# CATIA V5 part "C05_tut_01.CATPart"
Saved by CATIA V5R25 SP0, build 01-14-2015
Part number: Part1
Bounding box of the stored display mesh (mm): x -20 to 20, y 0 to 95, z 0 to 40
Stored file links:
  E:\ashutosh\Academics\Catia\CATIA V5-6R2013_partfiles\Tutorials_ver_2\C05_tut_01.CATPart
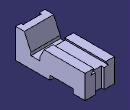
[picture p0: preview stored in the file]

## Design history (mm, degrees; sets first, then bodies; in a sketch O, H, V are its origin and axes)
Body1 (main body)
  Sketch1 on yz-plane, origin (0, 0, 0), H (0, 1, 0), V (0, 0, 1)
    point P1 (0, 0)
    line L1 (0, 0) -> (0, 40)
    line L2 (0, 40) -> (12, 40)
    line L3 (12, 40) -> (21, 20)
    line L4 (21, 20) -> (21, 16)
    line L5 (21, 16) -> (33, 16)
    line L6 (33, 16) -> (33, 20)
    point P7 (33, 20)
    line L7 (33, 20) -> (39, 32)
    point P8 (39, 32)
    line L8 (39, 32) -> (95, 32)
    line L9 (95, 32) -> (95, 0)
    point P10 (95, 0)
    line L10 (95, 0) -> (79, 0)
    line L11 (79, 0) -> (79, 6)
    line L12 (79, 6) -> (47, 6)
    line L13 (47, 6) -> (47, 0)
    point P14 (47, 0)
    line L14 (47, 0) -> (0, 0)
    reference intersected line E1 through (0, 0) direction (0, 1) from zx-plane
    length L1 = 40
    length L2 = 12
    length L8 = 56
    distance P8 P7 V = 12
    distance L1 L9 = 95
    distance P8 P7 H = 6
    length L9 = 32
    length L12 = 32
    length L11 = 6
    length L4 = 4
    distance L5 L14 = 16
    length L5 = 12
    distance L11 L9 = 16
    coincidence: P1 H, P10 H, P14 H, L1 E1
    vertical: L1 V, L4 V, L6 V, L9 V, L11 V, L13 V
    horizontal: L2 H, L5 H, L8 H, L10 H, L12 H, L14 H
  Pad1: profile Sketch1, direction (1, 0, 0), length 20, mirrored extent
  Sketch2 on face of Pad1 from Sketch1.L9, origin (0, 95, 0), H (-1, 0, 0), V (0, 0, 1)
    point P1 (-8, 32)
    line L1 (-8, 32) -> (-12, 26)
    point P2 (-12, 26)
    line L2 (-12, 26) -> (12, 26)
    point P3 (12, 26)
    line L3 (12, 26) -> (8, 32)
    point P4 (8, 32)
    line L4 (8, 32) -> (-8, 32)
    length L4 = 16
    length L2 = 24
    distance L4 L2 = 6
    distance L2 H = 26
    horizontal: L2 H, L4 H
    symmetry: P4 P1 V, P3 P2 V
  Pocket1: profile Sketch2, direction (0, -1, 0), through (limit type 6)
  Sketch3 on face of Pad1 from Sketch1.L9, origin (0, 95, 0), H (-1, 0, 0), V (0, 0, 1)
    line L1 (-6, 26) -> (6, 26)
    line L2 (6, 26) -> (6, -1.2781)
    line L3 (6, -1.2781) -> (-6, -1.2781)
    line L4 (-6, -1.2781) -> (-6, 26)
    reference projected line E1 (-12, 26) -> (12, 26) from edge [face of Pad1 from Sketch1.L9 | face of Pocket1 from Sketch2.L2]
    distance V L2 = 6
    horizontal: L1 H, L3 H
    vertical: L2 V, L4 V
    symmetry: L4 L2 V
    coincidence: L1 E1
  Pocket2: profile Sketch3, direction (0, -1, 0), length 4
  Sketch4 on face of Pad1 from Sketch1.L2, origin (0, 0, 40), H (1, 0, 0), V (0, 1, 0)
    line L1 (-12.5, -1.6175) -> (12.5, -1.6175)
    line L2 (12.5, -1.6175) -> (12.5, 3)
    line L3 (12.5, 3) -> (-12.5, 3)
    line L4 (-12.5, 3) -> (-12.5, -1.6175)
    reference projected line E1 (-20, 0) -> (20, 0) from edge [face of Pad1 from Sketch1.L1 | face of Pad1 from Sketch1.L2]
    length L1 = 25
    distance E1 L3 = 3
    horizontal: L1 H, L3 H
    vertical: L2 V, L4 V
    symmetry: L4 L2 V
  Pocket3: profile Sketch4, direction (0, 0, -1), through (limit type 3)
